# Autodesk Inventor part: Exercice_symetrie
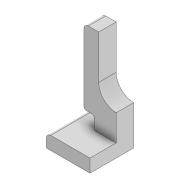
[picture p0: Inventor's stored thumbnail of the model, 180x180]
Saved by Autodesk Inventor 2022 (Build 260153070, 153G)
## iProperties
Created: 2021-03
Part Number: Exercice_symetrie
Material: Générique
Document SubType Name: Modeling
Designer: Fabian
Mass: 160.633 g
Surface Area: 306.779 cm^2
Volume: 160.633 cm^3
Density: 1 g/cm^3
Appearance: Par défaut
Author: Fabian
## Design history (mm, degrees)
sketch "Esquisse1"
  geometry: L1 (-20, 0)-(-20, 50); L2 (-20, 50)-(-37, 50); L3 (-37, 50)-(-37, -35); L4 (-37, -35)-(-25, -35); L5 (-25, -35)-(-25, -50); L6 (-25, -50)-(-50, -50); L7 (-50, -50)-(-50, -65); L8 (-50, -65)-(0, -65); L9 (0, 50)-(0, -65); L10 (-25, -50)-(0, -50); A1 r 20 centre (0, 0) between (-20, 0) and (0, -20); 2 further points
  constraints: 21 end point, 6 perpendicular, 4 point on line, 3 vertical, 2 point on circle, 1 centre point, 1 coincident, 1 horizontal, 1 midpoint, 1 tangent
  dimensions: "d0" = 40 diameter of A1; "d1" = 74 diameter of L3 L9; "d2" = 115 distance between parallel lines of L8 L2; "d3" = 30 distance between parallel lines of L8 L4; "d4" = 15 distance of L6.end L7.end; "d5" = 100 diameter of L7 L9; "d6" = 50 diameter of L5 L9; "d7" = 65 distance from line of L8 point (0, 0)
extrude "Extrusion1" new body sketch "Esquisse1" distance "d8" = 20; taper "d9" = 0 deg
extrude "Extrusion3" join sketch "Esquisse1" distance "d22" = 50; taper "d23" = 0 deg
fillet "Congé2" dims "d24" = 5, "d25" = 3
node "Solide1"
